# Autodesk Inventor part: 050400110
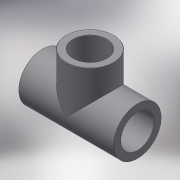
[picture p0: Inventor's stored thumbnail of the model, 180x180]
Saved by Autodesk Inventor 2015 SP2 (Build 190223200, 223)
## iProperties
Created: 2017-10
Part Number: 050400110
Material: Generic
Description: PLASSON TEE-CEMENT PVC 110
Document SubType Name: Modeling
Designer: KIM
Density: 1 g/cm^3
Appearance: Default
Author: KIM
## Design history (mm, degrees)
derived "050400.ipt"
feature "Solid1::050400.ipt"
feature "Solid2::050400.ipt"
tag "TaggingFeature1"
body "Solid1"
other parameters: "d0" = 239, "d1" = 129, "d2" = 61, "d5" = 99, "d7" = 1.1, "d8" = 61, "d10" = 129, "d12" = 99, "d15" = 0, "d17" = 0, "d19" = 99, "d21" = 61, "d22" = 0, "d23" = 61, "d24" = 1.1, "E_" = 129, "H_" = 239, "l_" = 61, "Z_" = 59
